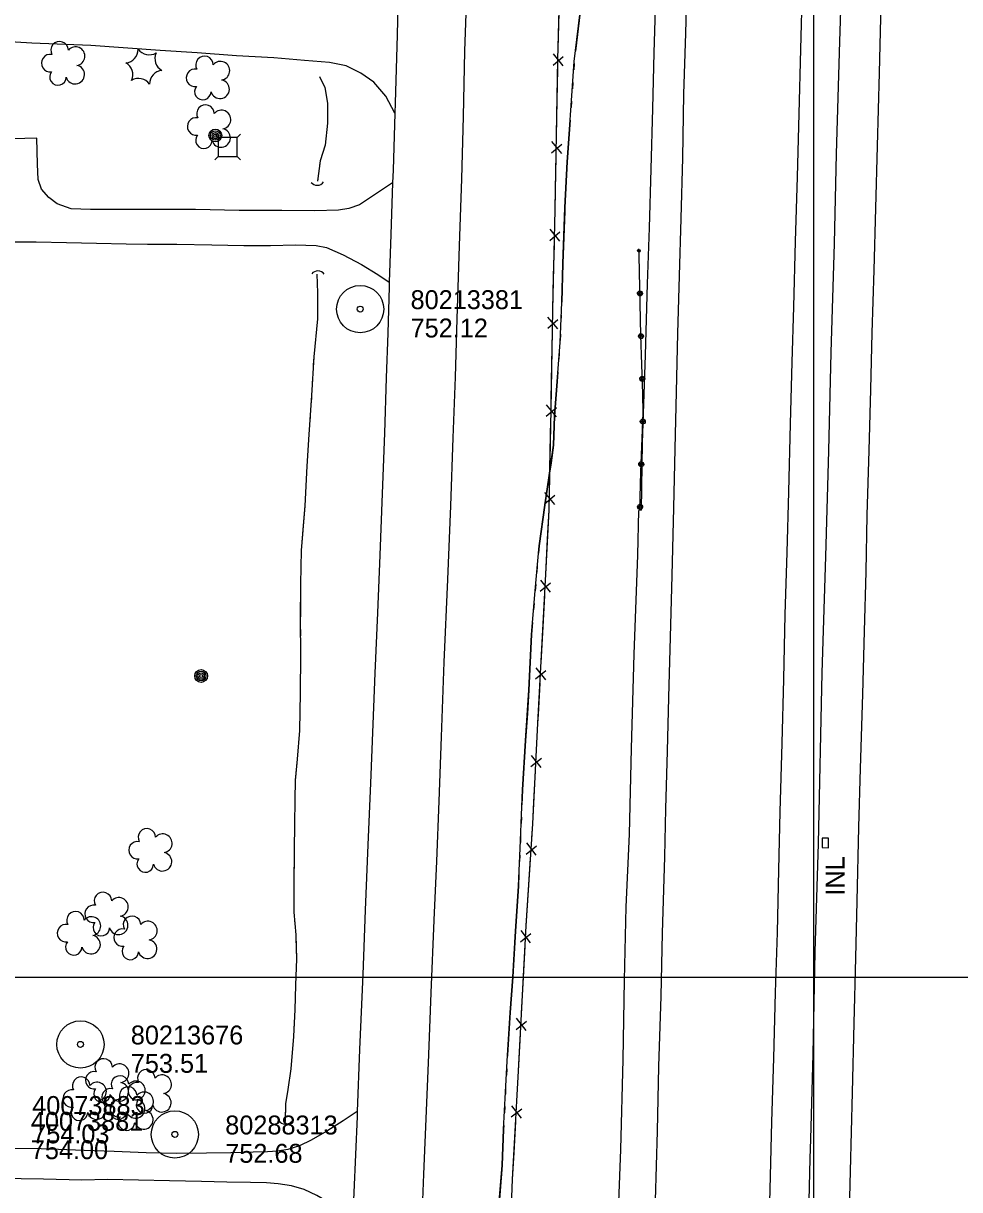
# Model space of a CAD drawing. Extents: x 591954 to 597000, y 198576 to 213500.
# Drawn here: x 593749 to 594046.3, y 199932.5 to 200302.8 of the extents above; entities that cross this region are included whole.
import ezdxf

# ---------------------------------------------------------------- set-up
doc = ezdxf.new("R2010")
doc.units = 0
for name, color, linetype in [('Level 10', 7, 'Continuous'), ('Level 11', 7, 'Continuous'), ('Level 14', 7, 'Continuous'), ('Level 15', 7, 'Continuous'), ('Level 17', 7, 'Continuous'), ('Level 18', 7, 'Continuous'), ('Level 19', 7, 'Continuous'), ('Level 21', 7, 'Continuous'), ('Level 6', 7, 'Continuous')]:
    doc.layers.add(name, color=color, linetype=linetype)

msp = doc.modelspace()

# ---------------------------------------------------------------- linework, layer by layer
at = {"layer": 'Level 10'}
for p, q in [((594000, 200000), (594000, 201500)), ((594000, 200000), (594000, 201500)), ((594000, 199500), (594000, 201000)), ((593500, 200000), (595000, 200000)), ((593500, 200000), (595000, 200000))]:
    msp.add_line(p, q, dxfattribs=at)
at = {"layer": 'Level 11'}
for points in [[(593945.21, 200148.23), (593945.57, 200169.59), (593946.56, 200197.39), (593947.14, 200220.03), (593947.78, 200237.8), (593948.29, 200256.46), (593948.8, 200275.71), (593949.27, 200293.43), (593949.75, 200310.99), (593950.25, 200327.25), (593950.63, 200344.2), (593951.05, 200360.13), (593951.48, 200376.26), (593951.92, 200393.04), (593952.41, 200410.16), (593952.86, 200424.96), (593953.22, 200443.73), (593953.78, 200464.14), (593954.37, 200483.78), (593955.49, 200506.75), (593955.76, 200527.61), (593956.21, 200546.62), (593956.28, 200548.49)], [(593949.66, 199929.05), (593950.29, 199951.08), (593950.74, 199971.59), (593951.48, 199993.9), (593951.96, 200013.97), (593952.68, 200038.12), (593952.99, 200053.43), (593953.53, 200071.72), (593953.89, 200088.77), (593954.41, 200107.94), (593954.93, 200127.48), (593955.47, 200149.01), (593955.89, 200167.65), (593956.37, 200185.79), (593956.81, 200204.32), (593957.3, 200222.64), (593957.8, 200240.77), (593958.33, 200260.07), (593958.73, 200280.26), (593959.29, 200299.66), (593959.82, 200319.63)], [(593868.13, 200317.27), (593867.64, 200299.15), (593867.07, 200277.4), (593866.96, 200274.22)], [(593985.62, 199913.32), (593986.08, 199932.56), (593986.65, 199954.07), (593987.29, 199974.29), (593987.79, 199995.08), (593988.38, 200014.15), (593988.82, 200033.99), (593989.26, 200052.45), (593989.89, 200074.22), (593990.4, 200094.58), (593990.87, 200115.09), (593991.49, 200134.8), (593992.04, 200154.01), (593992.6, 200175.62), (593993.1, 200195.18), (593993.6, 200212.77), (593994.16, 200233.46), (593994.75, 200254.02), (593995.28, 200274.01), (593995.84, 200294.59), (593996.37, 200314.61)], [(593889.65, 200311.96), (593889.04, 200293.88), (593888.61, 200273.2), (593888.04, 200253.42), (593887.39, 200232.08), (593886.62, 200208.92), (593886.05, 200190.49), (593885.33, 200171.23), (593884.6, 200149.55), (593883.61, 200126.21), (593882.52, 200100.01), (593881.6, 200076.25), (593880.93, 200055.89), (593880.18, 200036.82), (593879.33, 200018.05), (593878.4, 199995), (593877.62, 199975.44), (593876.83, 199957.51), (593875.98, 199937.4), (593875.32, 199918.16)], [(594011.04, 199917.42), (594011.58, 199938.39), (594012.26, 199963.35), (594012.77, 199985.34), (594013.28, 200006.13), (594013.71, 200024.11), (594014.29, 200047.6), (594014.73, 200066.25), (594015.51, 200089.8), (594016.05, 200109.79), (594016.6, 200128.63), (594016.91, 200146.67), (594017.57, 200167.14), (594018.05, 200186.53), (594018.44, 200204.56), (594019.14, 200224.4), (594019.63, 200244.04), (594020.21, 200263.77), (594020.76, 200287.1), (594021.35, 200308.94)], [(593866.96, 200274.22), (593866.36, 200256.16), (593866.23, 200252.15)], [(593866.23, 200252.15), (593865.68, 200235.76), (593865.16, 200220.61)], [(593865.16, 200220.61), (593865.11, 200219.16), (593864.7, 200204.43), (593864.21, 200190.25), (593863.62, 200172.65), (593862.92, 200153.54), (593862.11, 200133.94), (593861.42, 200115.58), (593860.62, 200096.47), (593859.98, 200080.26), (593859.16, 200061.6), (593858.38, 200041.98), (593857.5, 200021.24), (593856.73, 200000.8), (593855.67, 199977.05), (593854.99, 199957.33)], [(593945.21, 200148.23), (593944.41, 200148.11)], [(593854.99, 199957.33), (593854.94, 199955.73), (593853.92, 199931.6), (593853.46, 199921.83)]]:
    msp.add_lwpolyline(points, dxfattribs=at)
at = {"layer": 'Level 14'}
for centre, radius in [((593809.93, 200267.15), 2.02), ((593809.93, 200267.16), 1.52), ((593809.93, 200267.12), 1.01), ((593809.94, 200267.13), 0.502), ((593805.42, 200095.58), 2.02), ((593805.41, 200095.59), 1.52), ((593805.42, 200095.55), 1.01), ((593805.42, 200095.56), 0.502)]:
    msp.add_circle(centre, radius, dxfattribs=at)
at = {"layer": 'Level 15'}
for p, q in [((593917.19, 200289.53), (593920.42, 200292.26)), ((593920.42, 200289.29), (593917.26, 200293.08)), ((593916.69, 200261.67), (593919.91, 200264.41)), ((593919.92, 200261.45), (593916.75, 200265.22)), ((593916.11, 200233.83), (593919.35, 200236.55)), ((593919.35, 200233.58), (593916.2, 200237.38)), ((593915.46, 200205.96), (593918.68, 200208.71)), ((593918.7, 200205.74), (593915.52, 200209.51)), ((593915, 200178.11), (593918.22, 200180.85)), ((593918.24, 200177.88), (593915.07, 200181.66)), ((593914.47, 200150.26), (593917.69, 200152.99)), ((593917.7, 200150.03), (593914.53, 200153.81)), ((593913.08, 200122.49), (593916.39, 200125.11)), ((593916.3, 200122.14), (593913.26, 200126.03)), ((593911.59, 200094.67), (593914.91, 200097.29)), ((593914.82, 200094.32), (593911.78, 200098.21)), ((593910.14, 200066.84), (593913.45, 200069.47)), ((593913.37, 200066.51), (593910.33, 200070.38)), ((593908.58, 200039.05), (593911.93, 200041.63)), ((593911.8, 200038.66), (593908.81, 200042.58)), ((593910.05, 200010.88), (593907.01, 200014.76)), ((593906.83, 200011.22), (593910.14, 200013.85)), ((593905.4, 199983.4), (593908.71, 199986.03)), ((593908.62, 199983.06), (593905.58, 199986.94)), ((593907.13, 199955.23), (593904.1, 199959.12)), ((593903.91, 199955.58), (593907.23, 199958.2))]:
    msp.add_line(p, q, dxfattribs=at)
for points in [[(593998.04, 199911.2), (593998.79, 199942.44), (593999.01, 199948.59), (593999.74, 199975.56), (594000.41, 200007.96), (594001.47, 200042.41), (594002.59, 200096.53), (594003.81, 200133.52), (594004.74, 200167.07), (594005.48, 200198.31), (594006.49, 200232.91), (594007.16, 200261.32), (594008.21, 200296.97), (594009.61, 200340.21), (594010.46, 200373.31), (594011.16, 200409.19), (594012.2, 200442.5), (594013.14, 200480.71), (594014.13, 200513.93), (594015.08, 200550.51), (594015.11, 200551.22)], [(593903.07, 199904.6), (593904.3, 199935.86), (593906.12, 199968.21), (593908.59, 200016.22), (593910.72, 200048.69), (593912.35, 200080.62), (593914.87, 200127.94), (593915.93, 200148.22), (593916.54, 200180.24), (593917.06, 200211.78), (593917.86, 200243.58), (593918.72, 200291.25), (593919.54, 200322.96), (593920.05, 200370.41), (593921.01, 200402.93), (593922.05, 200435.58), (593922.8, 200467.33), (593922.92, 200515.05), (593923.69, 200546.97)], [(593918.81, 200294.75), (593919.1, 200306.07)], [(593918.48, 200278.22), (593918.67, 200288.17)], [(593918.28, 200266.9), (593918.48, 200278.22)], [(593917.98, 200250.36), (593918.16, 200260.32)], [(593917.74, 200239.04), (593917.86, 200243.58), (593917.98, 200250.36)], [(593917.33, 200222.51), (593917.58, 200232.46)], [(593917.05, 200211.19), (593917.06, 200211.78), (593917.33, 200222.51)], [(593916.78, 200194.65), (593916.94, 200204.61)], [(593916.59, 200183.34), (593916.78, 200194.65)], [(593916.28, 200166.8), (593916.48, 200176.76)], [(593916.07, 200155.48), (593916.28, 200166.8)], [(593915.44, 200138.96), (593915.93, 200148.22), (593915.94, 200148.9)], [(593929.16, 199620.44), (593929.91, 199629.52), (593930.7, 199652.08), (593931.34, 199674.3), (593932.06, 199699.72), (593932.57, 199723.8), (593933.37, 199745.23), (593934.11, 199774.51), (593935.25, 199818.21), (593936.13, 199847.19), (593936.78, 199874.71), (593937.44, 199901.93), (593938.05, 199928.56), (593938.7, 199945.25), (593939.43, 199973.79), (593939.87, 199998.99), (593940.42, 200022.32), (593941.39, 200045.33), (593942.12, 200072.52), (593942.89, 200102.5), (593944.06, 200133.9), (593944.41, 200148.11)], [(593914.85, 200127.65), (593914.87, 200127.94), (593915.44, 200138.96)], [(593913.97, 200111.13), (593914.5, 200121.08)], [(593913.37, 200099.83), (593913.97, 200111.13)], [(593912.49, 200083.31), (593913.02, 200093.26)], [(593911.91, 200072.01), (593912.35, 200080.62), (593912.49, 200083.31)], [(593911.07, 200055.49), (593911.57, 200065.43)], [(593910.42, 200044.19), (593910.72, 200048.69), (593911.07, 200055.49)], [(594004.65, 200044.06), (594002.65, 200044.1), (594002.59, 200041.1), (594004.59, 200041.06), (594004.65, 200044.06)], [(593909.34, 200027.68), (593909.99, 200037.62)], [(593908.6, 200016.39), (593909.34, 200027.68)], [(593907.75, 199999.87), (593908.26, 200009.81)], [(593907.17, 199988.57), (593907.75, 199999.87)], [(593906.32, 199972.05), (593906.83, 199981.99)], [(593905.7, 199960.74), (593906.12, 199968.21), (593906.32, 199972.05)], [(593904.77, 199944.23), (593905.33, 199954.17)], [(593904.18, 199932.93), (593904.3, 199935.86), (593904.77, 199944.23)]]:
    msp.add_lwpolyline(points, dxfattribs=at)
for centre, start, end in [((593842.27, 200253.85), 218.6794, 324.919), ((593842.52, 200221.69), 36.7794, 143.019), ((593832.2, 199955.81), 212.3794, 318.619)]:
    msp.add_arc(centre, 2.5, start, end, dxfattribs=at)
at = {"layer": 'Level 17'}
for points in [[(593866.96, 200274.22), (593864.09, 200279.6), (593860.24, 200284.11), (593856.12, 200286.98), (593851.42, 200289.26), (593846.21, 200290.38), (593838.2, 200290.98), (593828.52, 200291.8), (593816.67, 200292.47), (593804.11, 200293.38), (593792.46, 200294.15), (593770.39, 200295.74), (593751.68, 200296.46), (593736.03, 200297.38), (593718.66, 200298.33), (593700.52, 200299.26), (593687.58, 200300.3), (593683.36, 200300.55)], [(593866.23, 200252.15), (593861.44, 200248.93), (593855.71, 200245.15), (593852.3, 200243.94), (593849.08, 200243.44), (593841.54, 200243.19), (593831.07, 200243.3), (593817.48, 200243.31), (593803.65, 200243.69), (593787.94, 200243.7), (593770.29, 200243.65), (593764.2, 200243.91), (593759.71, 200245.47), (593757.05, 200247.44), (593754.68, 200250.15), (593753.69, 200253.17), (593753.46, 200258.1), (593753.28, 200266.27), (593733.85, 200265.78)], [(593718.69, 200233.56), (593726.72, 200233.43), (593735.86, 200233.53), (593744.07, 200233.39), (593753.05, 200233.41), (593762.64, 200233.24), (593772.18, 200233.02), (593781.6, 200232.77), (593788.34, 200232.7), (593797.7, 200232.61), (593808.84, 200232.42), (593819.02, 200232.28), (593827.45, 200232.21), (593835.4, 200232.49), (593841.95, 200232.29), (593845.27, 200231.64), (593850.51, 200229.3), (593856.36, 200226.21), (593861.5, 200222.99), (593865.16, 200220.61)], [(593944.76, 200148.23), (593945.06, 200160.35), (593945.74, 200179.08), (593945.65, 200185.16), (593945.07, 200203.81), (593944.46, 200228.95), (593944.35, 200231.19)], [(593944.76, 200148.23), (593945.06, 200160.35), (593945.74, 200179.08), (593945.65, 200185.16), (593945.07, 200203.81), (593944.46, 200228.95), (593944.35, 200231.19)], [(593854.99, 199957.33), (593850.54, 199954.36), (593845.34, 199951.1), (593840.34, 199948.18), (593836.66, 199946.42), (593832.92, 199945.25), (593829.65, 199944.71), (593826.52, 199944.48), (593821.94, 199944.37), (593814.89, 199944.23), (593807.13, 199944.11), (593797.54, 199944.01), (593788.01, 199944.25), (593777.8, 199944.63), (593768.29, 199944.99), (593754.64, 199945.43), (593736.8, 199945.66), (593721.67, 199946.19), (593709.78, 199946.32), (593706.23, 199946.87), (593702.51, 199948.46), (593699.85, 199949.29), (593698.02, 199949.36), (593696.19, 199949.37)], [(593853.46, 199921.83), (593850.32, 199925.44), (593846.5, 199928.07), (593842.2, 199930.71), (593838.14, 199932.55), (593834.12, 199933.77), (593829.9, 199934.41), (593826.14, 199934.66), (593821.07, 199934.75), (593813.55, 199934.84), (593805.51, 199935.07), (593795.36, 199935.33), (593785.51, 199935.48), (593775.65, 199935.7), (593767.49, 199935.49), (593755.4, 199935.82), (593741.1, 199936.08), (593726.45, 199936.82), (593717.4, 199936.82), (593708.4, 199936.97), (593704.69, 199936.82), (593701.27, 199936.1), (593698.81, 199935.79), (593695.74, 199935.85)]]:
    msp.add_lwpolyline(points, dxfattribs=at)
for centre, major_axis, ratio in [((593944.38, 200230.57), (0.025, 0.398), 0.998919), ((593944.75, 200217.01), (-0.789, -0.02), 0.999672), ((593944.75, 200217.01), (0.034, 0.397), 0.999715), ((593945.08, 200203.45), (-0.789, -0.023), 0.999791), ((593945.08, 200203.45), (-0.397, 0.032), 0.999198), ((593945.5, 200189.9), (-0.024, 0.79), 0.999538), ((593945.5, 200189.9), (0.032, 0.397), 0.999545), ((593945.64, 200176.34), (0.028, 0.789), 0.999982), ((593945.64, 200176.34), (-0.394, 0.058), 0.999408), ((593945.15, 200162.78), (0.029, 0.789), 0.999958), ((593945.15, 200162.78), (-0.394, 0.058), 0.999363), ((593944.78, 200149.23), (-0.789, 0.02), 0.999688), ((593944.78, 200149.23), (0.054, 0.394), 0.999684)]:
    msp.add_ellipse(centre, major_axis=major_axis, ratio=ratio, dxfattribs=at)
at = {"layer": 'Level 18'}
for centre, radius, start, end in [((593760.49, 200294.21), 2.78, 1.3946, 209.1675), ((593765.53, 200292.35), 2.97, 278.4237, 139.6575), ((593757.49, 200290.13), 2.78, 78.0716, 279.0826), ((593781.11, 200294.51), 4.3, 275.2113, 0.9762), ((593788.93, 200297.07), 4.3, 215.2113, 300.9762), ((593795.05, 200291.58), 4.3, 155.2113, 240.9762), ((593806.48, 200289.57), 2.78, 1.3946, 209.1675), ((593765.42, 200286.5), 2.97, 196.0745, 79.0477), ((593779.42, 200286.47), 4.3, 335.2113, 60.9762), ((593803.48, 200285.49), 2.78, 78.0716, 279.0826), ((593811.53, 200287.71), 2.97, 278.4237, 139.6575), ((593759.95, 200285.73), 2.61, 140.7797, 358.7123), ((593785.54, 200280.98), 4.3, 35.2113, 120.9762), ((593793.35, 200283.53), 4.3, 95.2113, 180.9762), ((593811.42, 200281.86), 2.97, 196.0745, 79.0477), ((593805.95, 200281.09), 2.61, 140.7797, 358.7123), ((593806.82, 200274.1), 2.78, 1.3946, 209.1675), ((593811.87, 200272.24), 2.97, 278.4237, 139.6575), ((593803.82, 200270.03), 2.78, 78.0716, 279.0826), ((593806.29, 200265.63), 2.61, 140.7797, 358.7123), ((593811.75, 200266.39), 2.97, 196.0745, 79.0477), ((593788.2, 200044.34), 2.78, 1.3946, 209.1675), ((593793.24, 200042.48), 2.97, 278.4237, 139.6575), ((593785.2, 200040.26), 2.78, 78.0716, 279.0826), ((593787.66, 200035.86), 2.61, 140.7797, 358.7123), ((593793.13, 200036.63), 2.97, 196.0745, 79.0477), ((593774.26, 200024.14), 2.78, 1.3946, 209.1675), ((593779.3, 200022.28), 2.97, 278.4237, 139.6575), ((593771.26, 200020.06), 2.78, 78.0716, 279.0826), ((593765.52, 200018.04), 2.78, 1.3946, 209.1675), ((593770.56, 200016.18), 2.97, 278.4237, 139.6575), ((593779.19, 200016.43), 2.97, 196.0745, 79.0477), ((593783.46, 200016.59), 2.78, 1.3946, 209.1675), ((593788.5, 200014.74), 2.97, 278.4237, 139.6575), ((593762.52, 200013.97), 2.78, 78.0716, 279.0826), ((593773.72, 200015.66), 2.61, 140.7797, 358.7123), ((593780.46, 200012.52), 2.78, 78.0716, 279.0826), ((593764.98, 200009.57), 2.61, 140.7797, 358.7123), ((593770.45, 200010.33), 2.97, 196.0745, 79.0477), ((593788.39, 200008.88), 2.97, 196.0745, 79.0477), ((593782.92, 200008.12), 2.61, 140.7797, 358.7123), ((593774.47, 199971.31), 2.78, 1.3946, 209.1675), ((593771.47, 199967.23), 2.78, 78.0716, 279.0826), ((593779.52, 199969.45), 2.97, 278.4237, 139.6575), ((593787.99, 199967.84), 2.78, 1.3946, 209.1675), ((593767.33, 199965.51), 2.78, 1.3946, 209.1675), ((593772.37, 199963.65), 2.97, 278.4237, 139.6575), ((593779.4, 199963.59), 2.97, 196.0745, 79.0477), ((593779.65, 199965.89), 2.78, 1.3946, 209.1675), ((593784.99, 199963.76), 2.78, 78.0716, 279.0826), ((593784.69, 199964.03), 2.97, 278.4237, 139.6575), ((593793.03, 199965.98), 2.97, 278.4237, 139.6575), ((593764.33, 199961.43), 2.78, 78.0716, 279.0826), ((593773.94, 199962.83), 2.61, 140.7797, 358.7123), ((593776.65, 199961.82), 2.78, 78.0716, 279.0826), ((593782.27, 199962.4), 2.78, 1.3946, 209.1675), ((593787.31, 199960.54), 2.97, 278.4237, 139.6575), ((593792.92, 199960.12), 2.97, 196.0745, 79.0477), ((593766.79, 199957.03), 2.61, 140.7797, 358.7123), ((593772.26, 199957.8), 2.97, 196.0745, 79.0477), ((593779.27, 199958.33), 2.78, 78.0716, 279.0826), ((593779.11, 199957.42), 2.61, 140.7797, 358.7123), ((593784.58, 199958.18), 2.97, 196.0745, 79.0477), ((593787.45, 199959.36), 2.61, 140.7797, 358.7123), ((593781.73, 199953.93), 2.61, 140.7797, 358.7123), ((593787.2, 199954.69), 2.97, 196.0745, 79.0477)]:
    msp.add_arc(centre, radius, start, end, dxfattribs=at)
at = {"layer": 'Level 19'}
for points in [[(593927.95, 200322.74), (593926.05, 200308.92), (593924.29, 200293.98)], [(593899.57, 199922.48), (593900.95, 199940.27), (593901.47, 199951.64), (593902.04, 199963.46), (593902.69, 199975.17), (593903.58, 199988.74), (593904.41, 199999.98), (593905.27, 200014.54), (593906.17, 200028.81), (593906.8, 200043.32), (593907.43, 200059.46), (593908.44, 200075.11), (593909.48, 200091.07), (593910.31, 200108.76), (593911.48, 200122.56), (593912.71, 200136.91), (593914.53, 200149.77), (593916.08, 200159.92), (593917.26, 200168.87), (593917.58, 200178.03), (593918.44, 200189.03), (593919.4, 200201.42), (593919.9, 200214.29), (593920.22, 200226.52), (593920.94, 200244.28), (593921.69, 200258.77), (593922.74, 200273.63), (593923.9, 200290.67), (593926.05, 200308.92)], [(593923.86, 200290), (593923.72, 200288.01)], [(593842.98, 200285.89), (593844.66, 200282.38), (593845.55, 200277.41), (593845.54, 200271.1), (593844.84, 200264.14), (593843.21, 200259.15), (593842.36, 200252.63)], [(593842.98, 200285.89), (593844.66, 200282.38), (593845.55, 200277.41), (593845.54, 200271.1), (593844.84, 200264.14), (593843.21, 200259.15), (593843.02, 200257.66)], [(593923.45, 200284.02), (593923.31, 200282.02)], [(593923.04, 200278.03), (593922.91, 200276.04)], [(593922.63, 200272.04), (593921.69, 200258.77), (593920.94, 200244.28), (593920.89, 200243.1)], [(593842.5, 200253.69), (593842.36, 200252.63)], [(593920.89, 200243.1), (593920.22, 200226.52), (593919.9, 200214.29), (593919.89, 200214.12)], [(593842.18, 200223.17), (593842.38, 200217.23), (593842.35, 200208.91), (593841.17, 200196.88), (593840.47, 200184.66), (593839.63, 200172.23), (593838.97, 200162.15), (593838.32, 200149.61), (593837.23, 200135.46), (593837.01, 200124.87), (593836.91, 200113.27), (593837.01, 200102.16), (593836.89, 200090.22), (593836.61, 200078.3), (593835.95, 200069.21), (593835.25, 200062.53), (593835.12, 200056.23), (593835.09, 200048.41), (593834.95, 200040.49), (593834.88, 200029.34), (593834.82, 200020.65), (593835.48, 200013.43), (593835.7, 200005.75), (593835.41, 199997.41), (593835.13, 199989.65), (593834.77, 199981.17), (593833.9, 199970.85), (593832.92, 199964.36), (593832.23, 199959.74), (593832.11, 199954.1)], [(593842.18, 200223.17), (593842.38, 200217.23), (593842.35, 200208.91), (593841.17, 200196.88), (593841.02, 200194.24)], [(593919.74, 200210.12), (593919.66, 200208.12)], [(593919.5, 200204.12), (593919.43, 200202.12)], [(593919.15, 200198.14), (593918.99, 200196.14)], [(593918.68, 200192.15), (593918.44, 200189.03), (593917.58, 200178.03), (593917.26, 200168.87), (593916.52, 200163.25)], [(593840.79, 200190.25), (593840.67, 200188.25)], [(593840.44, 200184.26), (593840.31, 200182.26)], [(593840.04, 200178.27), (593839.91, 200176.27)], [(593839.64, 200172.28), (593839.63, 200172.23), (593838.97, 200162.15), (593838.32, 200149.61), (593837.84, 200143.34)], [(593916.52, 200163.25), (593916.08, 200159.92), (593914.53, 200149.77), (593912.71, 200136.91), (593912.51, 200134.53)], [(593837.84, 200143.34), (593837.23, 200135.46), (593837.01, 200124.87), (593836.92, 200114.37)], [(593912.16, 200130.55), (593911.99, 200128.56)], [(593911.65, 200124.57), (593911.48, 200122.58)], [(593911.14, 200118.59), (593910.97, 200116.6)], [(593836.94, 200110.37), (593836.95, 200108.37)], [(593910.64, 200112.61), (593910.31, 200108.76), (593909.48, 200091.07), (593909, 200083.66)], [(593836.99, 200104.37), (593837.01, 200102.37)], [(593836.97, 200098.37), (593836.95, 200096.37)], [(593836.91, 200092.37), (593836.89, 200090.22), (593836.61, 200078.3), (593835.95, 200069.21), (593835.34, 200063.43)], [(593909, 200083.66), (593908.44, 200075.11), (593907.43, 200059.46), (593907.24, 200054.72)], [(593835.34, 200063.43), (593835.25, 200062.53), (593835.12, 200056.23), (593835.09, 200048.41), (593834.95, 200040.49), (593834.91, 200034.43)], [(593907.09, 200050.72), (593907.01, 200048.72)], [(593906.86, 200044.72), (593906.8, 200043.32), (593906.78, 200042.73)], [(593906.6, 200038.73), (593906.52, 200036.73)], [(593906.34, 200032.74), (593906.17, 200028.81), (593905.27, 200014.54), (593904.64, 200003.79)], [(593834.89, 200030.43), (593834.88, 200029.34), (593834.87, 200028.43)], [(593834.84, 200024.43), (593834.83, 200022.43)], [(593835.02, 200018.44), (593835.2, 200016.45)], [(593835.51, 200012.47), (593835.7, 200005.75), (593835.41, 199997.41), (593835.13, 199989.65), (593834.87, 199983.48)], [(593904.64, 200003.79), (593904.41, 199999.98), (593903.58, 199988.74), (593902.69, 199975.17), (593902.67, 199974.85)], [(593834.87, 199983.48), (593834.77, 199981.17), (593833.9, 199970.85), (593832.92, 199964.36), (593832.23, 199959.74), (593832.12, 199954.65)], [(593902.45, 199970.86), (593902.34, 199968.86)], [(593902.11, 199964.87), (593902.04, 199963.46), (593902.01, 199962.87)], [(593901.82, 199958.88), (593901.72, 199956.88)], [(593901.53, 199952.88), (593901.47, 199951.64), (593900.95, 199940.27), (593899.68, 199923.95)]]:
    msp.add_lwpolyline(points, dxfattribs=at)
at = {"layer": 'Level 21'}
for p, q in [((593810.83, 200266.52), (593809.77, 200267.58)), ((593816.83, 200266.52), (593817.89, 200267.58)), ((593809.77, 200259.46), (593810.83, 200260.52)), ((593817.89, 200259.46), (593816.83, 200260.52))]:
    msp.add_line(p, q, dxfattribs=at)
msp.add_lwpolyline([(593810.83, 200260.52), (593816.83, 200260.52), (593816.83, 200266.52), (593810.83, 200266.52)], close=True, dxfattribs=at)
at = {"layer": 'Level 6'}
for centre, radius in [((593855.92, 200212.04), 7.5), ((593855.92, 200212.04), 7.5), ((593855.92, 200212.04), 0.96), ((593855.92, 200212.04), 0.96), ((593767.1, 199978.61), 7.5), ((593767.1, 199978.61), 0.96), ((593797.07, 199950.04), 7.5), ((593797.07, 199950.04), 0.96)]:
    msp.add_circle(centre, radius, dxfattribs=at)

# ---------------------------------------------------------------- texts
at = {"layer": 'Level 15'}
msp.add_text('INL', height=6, rotation=90, dxfattribs=at).set_placement((594009.71, 200025.86))
at = {"layer": 'Level 6'}
for s, p in [('80213381', (593871.92, 200212.04)), ('80213381', (593871.92, 200212.04)), ('752.12', (593871.92, 200203.04)), ('752.12', (593871.92, 200203.04)), ('80213676', (593783.09, 199978.61)), ('753.51', (593783.09, 199969.61)), ('40073883', (593751.78, 199956.22)), ('40073881', (593751.34, 199951.2)), ('80288313', (593813.07, 199950.04)), ('754.03', (593751.78, 199947.22)), ('754.00', (593751.34, 199942.2)), ('752.68', (593813.07, 199941.04))]:
    msp.add_text(s, height=6, dxfattribs=at).set_placement(p)

doc.saveas('drawing.dxf')
